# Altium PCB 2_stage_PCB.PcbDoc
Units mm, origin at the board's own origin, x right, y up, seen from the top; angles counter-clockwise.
Board outline 44.2 x 64.2 mm, 2 copper layers (M1(Top_copper), M2(Bottom copper), stack 0.325 mm thick; 22 components, 5 nets, 100 pads, 1 vias.
Unrouted connection lines stored in the file: 2.
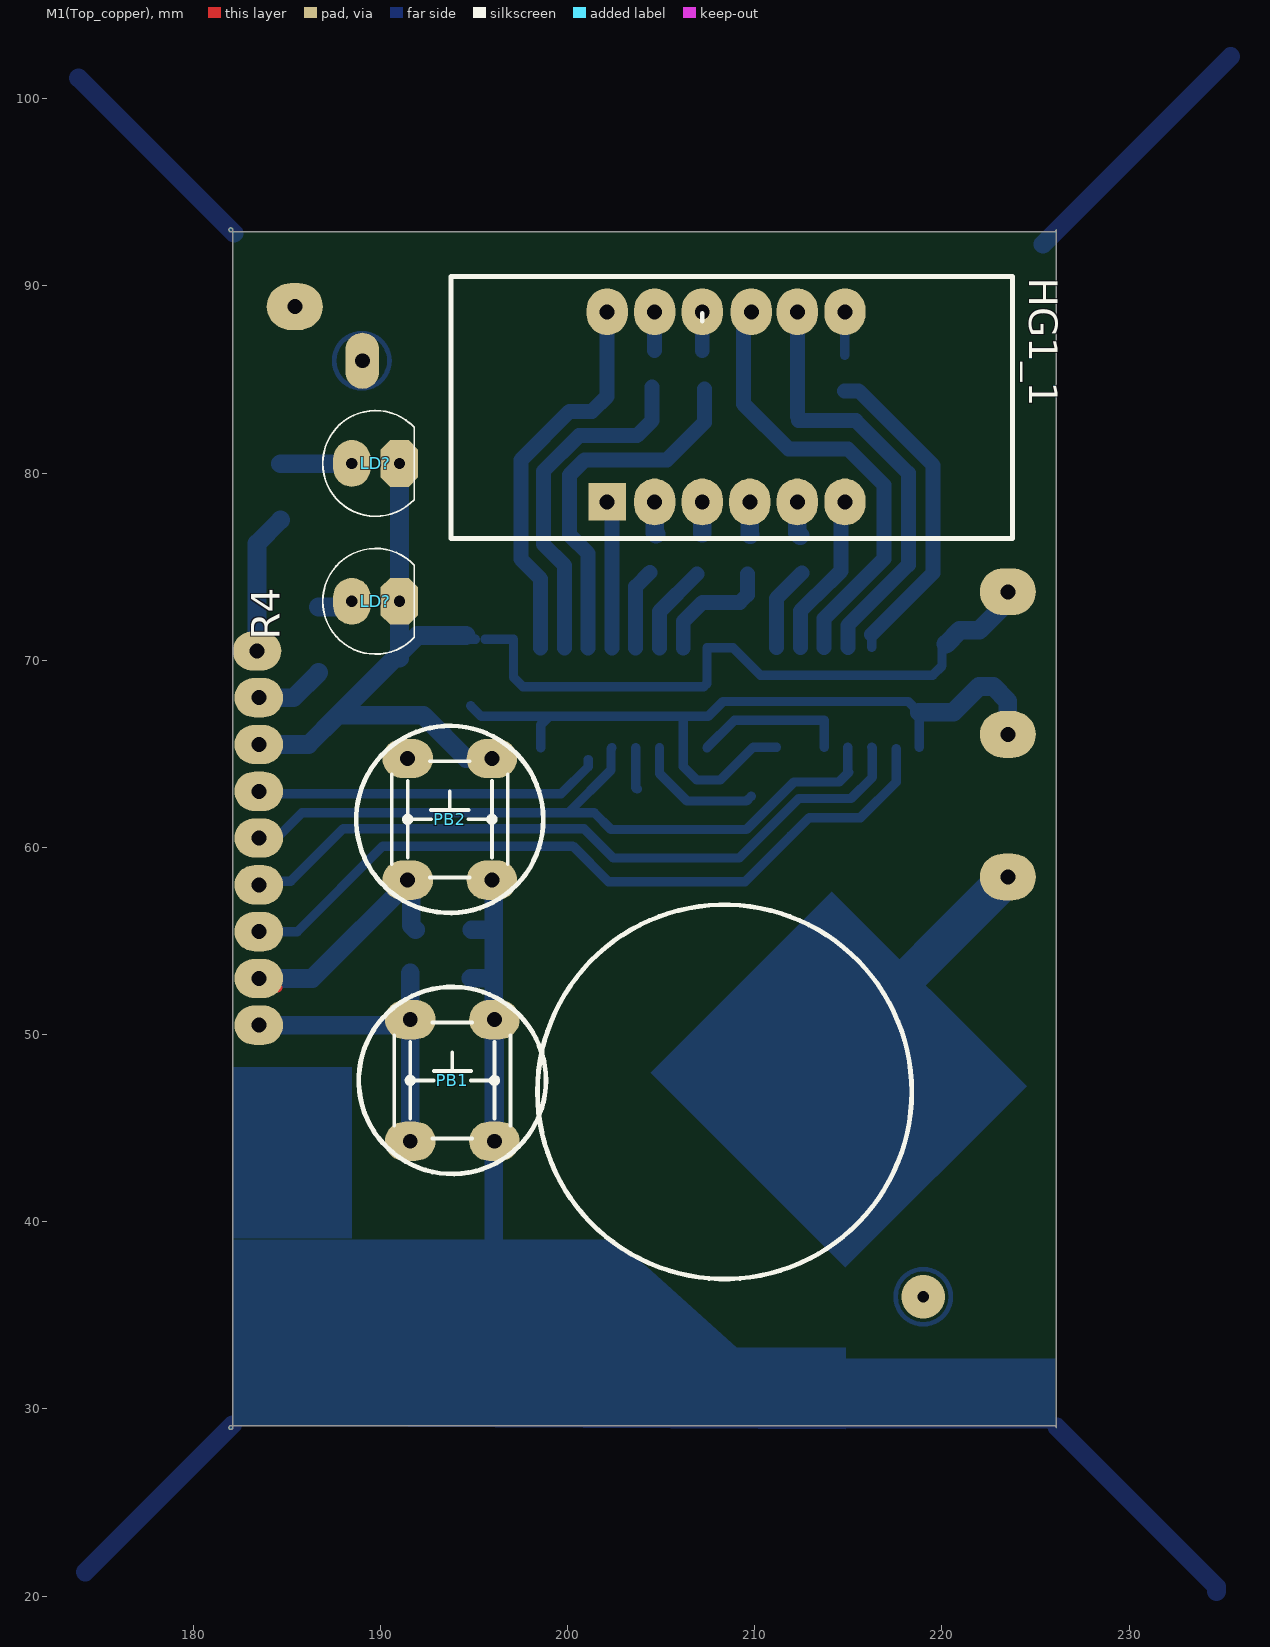
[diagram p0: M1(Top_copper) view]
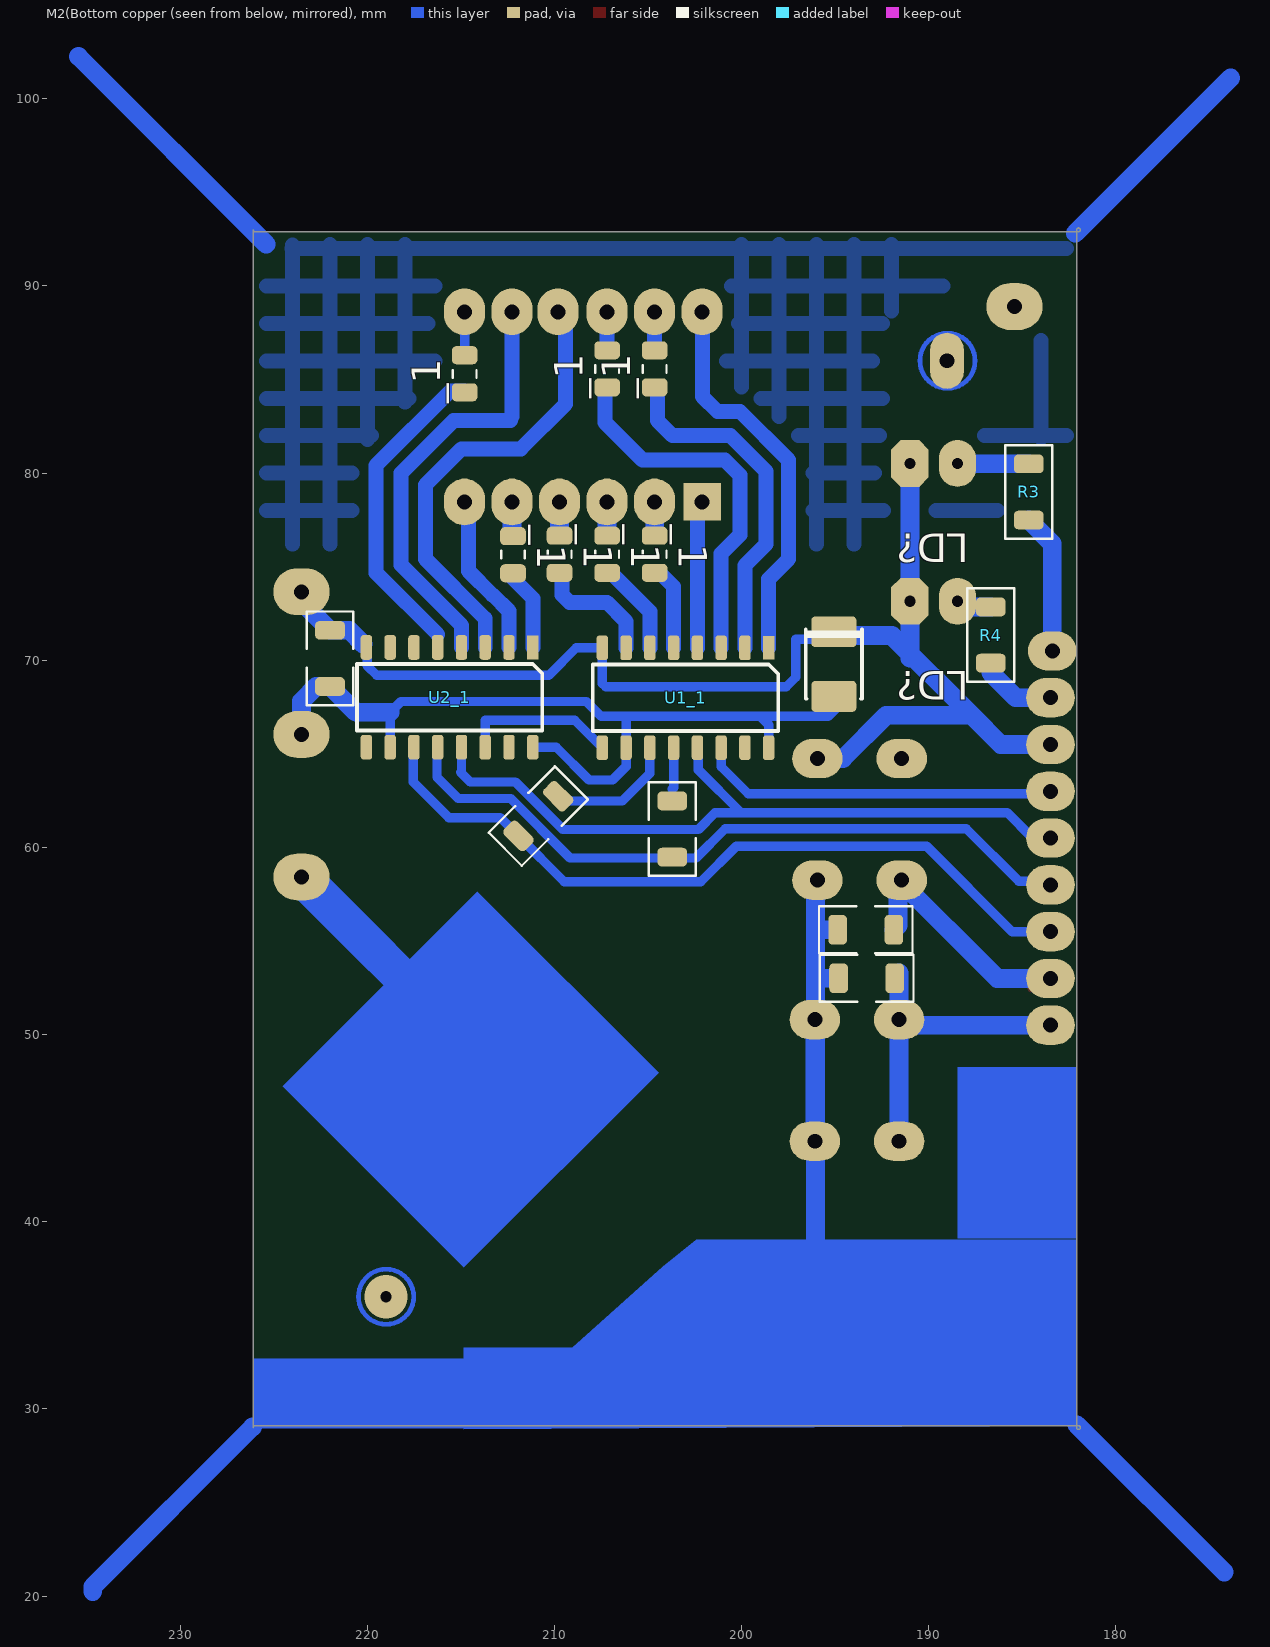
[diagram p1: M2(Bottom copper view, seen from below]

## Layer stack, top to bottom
Top Solder: solder mask 0.0102, Solder Resist, Dk 3.5
M1(Top_copper): signal copper 0.0356
Dielectric 1: core 0.254, FR-4, Dk 4.2
M2(Bottom copper: signal copper 0.0356
Bottom Solder: solder mask 0.0102, Solder Resist, Dk 3.5

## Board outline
181.9,29 cw(c182,29) 182,29.1 226,29.1 cw(c226,29) 226.1,29 226.1,93 cw(c226,93) 226,92.9 182,92.9 cw(c182,93) 181.9,93 cw(c182,93) 182,93.1 cw(c182,93) 182.1,93 182.1,29 cw(c182,29) 182,28.9 cw(c182,29)

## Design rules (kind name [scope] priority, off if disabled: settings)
AssemblyTestPointUsage [All] p1 off:
AssemblyTestpoint [All] p1 off: testpointundercomponent=TRUE minsize=1.016 maxsize=2.54 preferedsize=1.524 minholesize=0 maxholesize=1.016 preferedholesize=0.813 testpointgrid=0.025 usegrid=TRUE gridtolerance=0 allowsidetop=TRUE allowsidebottom=TRUE
Clearance Clearance_GND [All vs InNet('No Net')] p1 off: gap=0.254 except(0.5: Track-Poly SMDPad-Poly THPad-Poly Via-Poly Fill-Poly Poly-Poly; 0.7: Track-Region SMDPad-Region THPad-Region Via-Region Fill-Region Poly-Region Region-Region; 1: Arc-Fill Arc-Poly Arc-Region)
Clearance isairon_rule [All] p2 off: gap=0.254 // Для изучения
Clearance [All] p3: gap=2 except(0.254: Arc-Arc Arc-Track Arc-SMDPad Arc-THPad Arc-Via Track-Track Track-SMDPad Track-THPad Track-Via SMDPad-SMDPad SMDPad-THPad SMDPad-Via THPad-THPad THPad-Via Via-Via; 0.5: Track-Poly SMDPad-Poly THPad-Poly Via-Poly Fill-Poly Poly-Poly)
ComponentClearance [All] p1: gap=0.5 collisioncheckmode=3 verticalgap=0.5 showdistances=FALSE
FabricationTestPointUsage [All] p1 off: valid=0 allowmultiple=FALSE
FabricationTestpoint [All] p1 off: side=3 testpointundercomponent=TRUE minsize=1.016 maxsize=2.54 preferedsize=1.524 minholesize=0 maxholesize=1.016 preferedholesize=0.813 testpointgrid=0.025 allowsidetop=TRUE allowsidebottom=TRUE usegrid=TRUE gridtolerance=0
PasteMaskExpansion [All] p1 off: expansion=0
PolygonConnect [All] p1: connectstyle=Relief reliefconductorwidth=0.254 reliefentries=4 polygonreliefangle="90 Angle" airgapwidth=0.254
RoutingVias [All] p1: holewidth=0.6 width=2.1 viastyle="Through Hole" minholewidth=0.5 minwidth=1.9 maxholewidth=1.5 maxwidth=2.2
SolderMaskExpansion [All] p1 off: expansion=0.102
Width [All] p1: maxlimit=1 minlimit=0.254 preferedwidth=0.5
24 further rules are at their usual default settings.

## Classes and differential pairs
component class 2_stage_Sheet: LD? PB1 PB2 PB?

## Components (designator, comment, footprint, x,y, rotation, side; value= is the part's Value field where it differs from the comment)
_1 "Comment" 0805 204.65,75.666 r90 bottom
_1 "Comment" 0805 207.19,75.666 r90 bottom
_1 "Comment" 0805 209.73,75.666 r90 bottom
_1 "Comment" 0805 212.217,75.641 r90 bottom
_1 "Comment" 0805 214.8,85.309 r270 bottom
_1 "Comment" 0805 204.65,85.572 r270 bottom
_1 "Comment" 0805 207.19,85.572 r270 bottom
HG1_1 "CC36-12" FYQ_3641AG-11 208.46,83.54 r0 top locked (schematic designator HG1)
LD? "Led" "Led d5mm" 189.738,73.152 r0 top
LD? "Led" "Led d5mm" 189.738,80.518 r0 top
PB1 "Push Button" PB_ALPS_SKHHDTA010 193.838,47.55 r270 top
PB2 "Push Button" PB_ALPS_SKHHDTA010 193.7,61.5 r270 top
R3 "1k" R1206 184.658,78.994 r90 bottom
R4 "1k" R1206 186.69,71.35 r90 bottom (schematic designator R3)
U1_1 "74HC595" SO16-150 203,68 r0 bottom (schematic designator U1)
U2_1 "74HC595" SO16-150 215.606,68.021 r0 bottom (schematic designator U2)
? "Comment" C1206(3216) 203.708,60.984 r90 bottom
? "Comment" C1206(3216) 210.865,61.677 r315 bottom
? "Comment" C1206(3216) 221.996,70.104 r270 bottom
? "Comment" "EL Case B (3528-21)" 195.072,69.797 r270 bottom
? "Comment" C1206(3216) 193.321,53.01 r0 bottom
? "Comment" C1206(3216) 193.37,55.601 r0 bottom

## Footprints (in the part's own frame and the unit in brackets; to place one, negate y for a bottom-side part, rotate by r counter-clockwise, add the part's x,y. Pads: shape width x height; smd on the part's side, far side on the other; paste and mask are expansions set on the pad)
0805 [mil] "Metal Electrode Face (MELF) Resistor; Body 2 x 1.4 mm (LxDia)"
  rrect50% 38x54 smd: 1(-39,0) 2(39,0)
  silkscreen extent -8,-25 8,25, body extent -39,-25 39,25, height 19
C1206(3216) [mm]
  rrect50% 1x1.6 smd: 1(-1.5,0) 2(1.5,0)
  silkscreen extent -2.5,-1.25 2.5,1.25, body extent -1.6,-0.8 1.6,0.8, height 1
"EL Case B (3528-21)" [mm] "Capacitor, SM Tantalum; Body 3.5 x 2.8 mm (LxW typ)"
  rrect25% 1.65x2.4 smd: 1(-1.725,0) 2(1.725,0)
  silkscreen extent -1.85,-1.5 1.85,1.5, body extent -1.75,-1.4 1.75,1.4, height 1.91
FYQ_3641AG-11 [mm] "Four Digit 0.36\" Seven Segment Display"
  rect 2x2 hole 0.8: 1(-6.35,-5.08)
  oval 2.2x2.5 hole 0.8: 2(-3.81,-5.08) 3(-1.27,-5.08) 4(1.27,-5.08) 5(3.81,-5.08) 6(6.35,-5.08) 7(6.35,5.08) 8(3.81,5.08) 9(1.35,5.08) 10(-1.27,5.08) 11(-3.81,5.08) 12(-6.35,5.08)
  silkscreen extent -14.7,-7.03 15.3,6.97, body extent -14.75,-6.86 15.25,7.14, height 7.23
"Led d5mm" [mm]
  oval 2x2.5 hole 0.6: 1(-1.27,0)
  oct 2x2.5 hole 0.6: 2(1.27,0)
  silkscreen extent -2.83,-2.82 2.06,2.82, body extent -2.97,-3 2.45,3.02, height 12.31
PB_ALPS_SKHHDTA010 [mm] "6x6mm Model, 13mm Stem Height Vertical Pushbutton Switch, ALPS SKHH Series"
  oval 2.1x2.7 hole 0.8: 1(-3.25,2.25) 2(3.25,2.25) 3(-3.25,-2.25) 4(3.25,-2.25)
  silkscreen extent -3.1,-3.1 3.1,3.1, body extent -3.95,-3.1 3.95,3.1, height 13
R1206 [mm]
  rrect50% 1x1.6 smd: 1(-1.5,0) 2(1.5,0)
  silkscreen extent -2.5,-1.25 2.5,1.25, body extent -1.6,-0.8 1.6,0.8, height 0.6
SO16-150 [mil]
  rect 24x50 smd mask+4: 1(-175,-105)
  rrect50% 24x52 smd mask+4: 2(-125,-105) 3(-75,-105) 4(-25,-105) 5(25,-105) 6(75,-105) 7(125,-105) 8(175,-105) 9(175,105) 10(125,105) 11(75,105) 12(25,105) 13(-25,105) 14(-75,105) 15(-125,105) 16(-175,105)
  silkscreen extent -195,-70 195,70, body extent -195,-122 195,122, height 67

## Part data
HG1_1: "30mA Forvard current"
LD? LD?: library part Led-5mm, "5mm"
PB1 PB2: library part PB_ALPS_SKHHDTA010, "Push-Button Switch SPDT"
R3 R4: library part R-1206-1%, "SMD 1206 0.125W 1% 200V"

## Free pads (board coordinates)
  oval 2.6x2.1 hole 0.8 unplated: 23(183.5,50.5) 24(183.5,53) 25(183.5,55.5) 26(183.5,58) 27(183.5,60.5) 28(183.5,63) 29(183.5,65.5) 30(183.4,70.5) 30(183.5,68)
  oval 3x2.5 hole 0.8 unplated: 31(223.52,73.66) 32(223.52,66.04) 33(223.52,58.42) 34(185.42,88.9)
  oval 1.8x3 hole 0.8 unplated: 45(189.027,86.004)

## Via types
v1: diameter 2.3, hole 0.6, M1(Top_copper) to M2(Bottom copper, 1 vias

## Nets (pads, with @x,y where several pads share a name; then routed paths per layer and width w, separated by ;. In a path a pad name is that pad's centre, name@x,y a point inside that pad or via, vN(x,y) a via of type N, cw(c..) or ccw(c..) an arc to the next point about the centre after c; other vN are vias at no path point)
NetLD?_2: 
NetPB1_1: PB1.1 PB1.2 | length 6.5
  M2(Bottom copper w1: PB1.2 PB1.1
NetPB1_3: PB1.3 PB1.4 | length 9
  M2(Bottom copper w1: PB1.4 PB1.3 191.588,53.285 191.592,53.289
NetPB2_1: PB2.1 PB2.2 | length 27.7
  M2(Bottom copper w1: 187.706,67.056 192.278,67.056 194.584,64.75 PB2.1 ; 196.052,39.105 PB2.2@196.052,57.615
NetPB2_3: PB2.3 PB2.4
pads on no net: ?.1 ?.2 _1.1 _1.2 HG1_1.1 HG1_1.2 HG1_1.3 HG1_1.4 HG1_1.5 HG1_1.6 HG1_1.7 HG1_1.8 HG1_1.9 HG1_1.10 HG1_1.11 HG1_1.12 LD?.1 LD?.2 R3.1 R3.2 R4.1 R4.2 U1_1.1 U1_1.2 U1_1.3 U1_1.4 U1_1.5 U1_1.6 U1_1.7 U1_1.8 U1_1.9 U1_1.10 U1_1.11 U1_1.12 U1_1.13 U1_1.14 U1_1.15 U1_1.16 U2_1.1 U2_1.2 U2_1.3 U2_1.4 U2_1.5 U2_1.6 U2_1.7 U2_1.8 U2_1.9 U2_1.10 U2_1.11 U2_1.12 U2_1.13 U2_1.14 U2_1.15 U2_1.16
copper on no net: | length 570.4
  M1(Top_copper) w0.5: 183.5,55.5 184,55.5 ; 183.5,63 184,62.5 ; 183.9,70.5 183.979,70.5 ; 184,53 184.5,52.5 ; 184,58 184.18,58 ; 184,68 184.079,68
  M2(Bottom copper w0.254: 190.477,86.004 ccw(c189.001,86.004) 190.477,86.004 ; 220.474,35.992 ccw(c218.999,35.992) 220.474,35.992
  M2(Bottom copper w0.5: 183.2,63.2 183.535,62.865 195.135,62.865 199.644,62.865 201.095,64.316 201.095,64.697 ; 183.3,58 183.5,58.2 185.2,58.2 188,61 200.874,61 202.438,59.436 209.169,59.436 212.344,62.611 215.138,62.611 216.281,63.754 216.281,65.314 216.241,65.354 ; 183.5,55.5 185.548,55.5 190.119,60.071 200.279,60.071 202.184,58.166 209.475,58.166 211.925,60.617 212.904,61.595 214.63,61.595 215.646,61.595 217.551,63.5 217.551,65.278 ; 183.5,65.5 185.9,65.5 186,65.6 191.52,71.12 195.072,71.12 ; 183.8,60.5 184.452,60.5 185.801,61.849 194.649,61.849 200.025,61.849 ; 194.818,67.564 195.382,67 199,67 ; 195.58,71.12 197.104,71.12 197.104,69.088 197.612,68.58 207.264,68.58 207.445,68.761 207.445,70.667 208.833,70.667 210.3,69.2 219.5,69.2 220,69.7 220,70.637 220.051,70.688 ; 198.555,65.333 198.555,66.555 198.6,66.6 199,67 ; 202.1,78.3 202.365,78.035 ; 202.365,65.333 202.311,65.279 202.311,64.135 200.025,61.849 ; 203.635,65.333 203.635,63.192 203.708,63.119 ; 204.5,88.7 204.65,88.55 ; 204.905,65.333 204.905,63.954 206.375,62.484 209.55,62.484 209.804,62.738 ; 206.175,67 206.175,65.033 206.175,64.325 206.9,63.6 208.153,63.6 209.907,65.354 211.161,65.354 ; 207.445,65.333 208.912,66.8 212.1,66.8 213.7,66.8 213.7,65.355 ; 213.3,73.5 213.327,73.5 ; 214.5,78.5 214.6,78.4 ; 214.8,86.3 214.8,88.4 215,88.6 ; 214.971,65.354 214.971,64.048 215.011,64.008 214.503,63.5 212.09,63.5 209.55,60.96 202.311,60.96 201.422,61.849 200.025,61.849 ; 216.241,70.688 216.241,71.385 ; 218.781,65.354 218.781,67.219 218.2,67.8 208.3,67.8 207.5,67 199,67
  M2(Bottom copper w0.8: 198.555,70.667 198.555,74.345 197.5,75.4 197.5,80.7 200.1,83.3 201.3,83.3 202.1,84.1 202.1,88.5 ; 199.825,70.667 199.825,75.075 198.7,76.2 198.7,80.1 200.6,82 203.7,82 204.5,82.8 204.5,84.6 ; 201.095,70.667 201.095,75.705 200.1,76.7 200.1,79.9 200.9,80.7 205.3,80.7 207.3,82.7 207.3,84.5 ; 202.365,70.667 202.365,78.035 ; 203.635,70.667 203.635,73.935 204.4,74.7 ; 204.65,86.563 204.65,88.55 ; 204.905,70.667 204.905,72.605 206.9,74.6 ; 206.175,70.667 206.175,72.075 207.2,73.1 209.2,73.1 209.6,73.5 209.6,74.6 ; 207.19,86.563 207.19,88.62 ; 209.4,88.5 209.4,83.7 211.8,81.3 214.966,81.3 216.891,79.375 216.891,75.413 213.701,72.223 213.701,70.688 ; 211.161,70.688 211.161,73.312 212.524,74.675 ; 212.27,83.03 212.27,88.62 ; 212.344,82.8 215.396,82.8 218.2,79.996 218.2,75.1 214.971,71.871 214.971,70.688 ; 212.431,70.688 212.431,72.631 213.3,73.5 ; 213.327,73.5 214.6,74.773 214.6,78.4 ; 214.8,84.4 215.549,84.4 219.532,80.416 219.532,74.676 216.241,71.385
  M2(Bottom copper w1: 173.863,101.117 182.169,92.812 ; 174.219,21.285 182.093,29.159 ; 183.4,70.5 183.4,76.236 184.658,77.494 ; 183.5,50.5 191.288,50.5 191.588,50.8 ; 183.5,53 186.35,53 191.77,58.42 ; 183.5,68 185.348,68 186.69,69.342 ; 183.896,65.5 185.9,65.5 186.15,65.5 187.706,67.056 191.971,71.321 194.564,71.321 ; 184.658,80.494 188.444,80.494 188.468,80.518 ; 186.69,72.85 188.42,72.85 188.722,73.152 ; 191.008,70.104 191.008,80.518 ; 191.643,58.141 191.643,55.828 191.87,55.601 ; 194.821,53.01 195.961,53.01 195.986,52.984 ; 194.87,55.601 195.936,55.601 196.037,55.499 ; 204.65,78.46 204.65,76.807 204.724,76.733 ; 207.188,76.784 207.19,76.786 207.19,78.46 ; 209.73,78.46 209.73,76.731 209.753,76.708 ; 212.27,78.46 212.27,76.807 212.42,76.657 ; 214.376,47.498 214.884,47.498 ; 218.781,67.219 220.611,67.219 221.996,68.604 222.734,68.604 223.52,67.818 223.52,66.04 ; 220.218,70.866 220.956,71.604 221.996,71.604 223.52,73.128 223.52,73.66 ; 225.4,92.227 235.433,102.26 ; 226.136,29.032 234.671,20.498 234.671,20.244
  M2(Bottom copper w2: 214.884,49.784 223.52,58.42
  other v1: 218.999,35.992

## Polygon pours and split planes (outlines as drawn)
no net on M2(Bottom copper "NONET_L02_P002" (hatched 90Degree grid 2 track 0.8, remove dead copper, pour order 2): 182.651,92.278 182.702,92.227 225.4,92.227 225.4,75.133 225.628,74.905 224.333,76.2 182.651,76.2

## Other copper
M2(Bottom copper:
  rectangle net NetPB2_1: 214.853,28.956 226.06,32.69
  rectangle: 182.118,39.116 188.468,48.26
  region: 214.837,37.545 224.536,47.244 214.119,57.661 204.42,47.962
  region net NetPB2_1: 182.1,39.04 202.438,39.04 204.216,37.592 209.042,33.274 214.853,33.274 214.853,32.004 214.853,28.9 182.1,29.1 182.1,34.145 182.1,36.22

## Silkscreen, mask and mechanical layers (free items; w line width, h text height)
Top Overlay:
  circle w0.254: c208.382,46.939 r10
  circle w0.254: c193.838,47.55 r5
  circle w0.254: c193.7,61.5 r5
0 (Board_boarders):
  circle w0.254: c189,86 r1.5
  circle w0.254: c219,36 r1.5
  lines w0.2: 182,29 182,93 226,93 226,29 182,29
